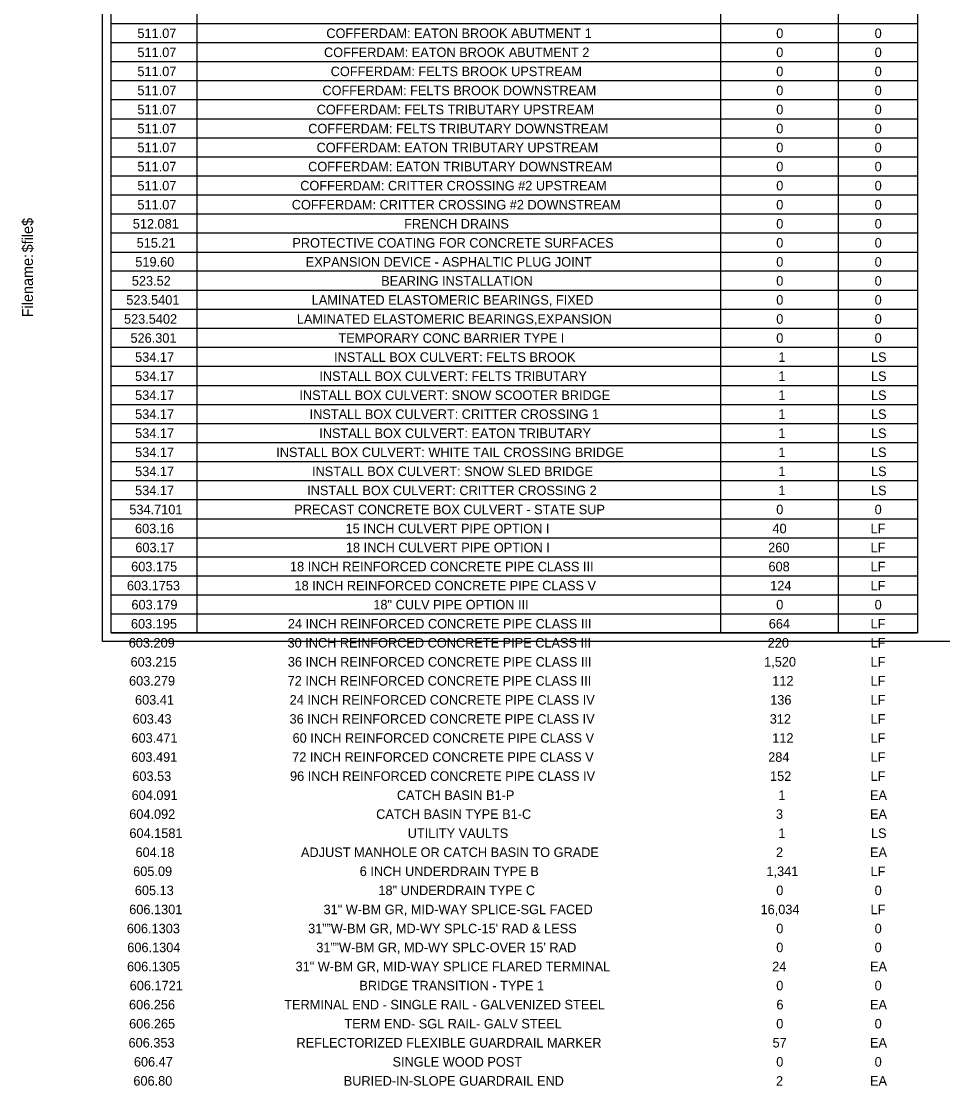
# Model space of a CAD drawing. Extents: x -18.7 to 5.6, y -2.7 to 4.
# Drawn here: x -0.084 to 0.868, y -0.459 to 0.641 of the extents above; entities that cross this region are included whole.
import ezdxf

# ---------------------------------------------------------------- set-up
doc = ezdxf.new("R2010")
doc.units = 0
doc.layers.add('ANNOTATION', color=7, linetype='Continuous')
doc.layers.add('BORDER', color=7, linetype='Continuous')

msp = doc.modelspace()

# ---------------------------------------------------------------- linework, layer by layer
at = {"layer": 'BORDER'}
for p, q in [((0.0974, 1.7215), (0.0974, 0.0088)), ((0.6387, 1.7215), (0.6387, 0.0088)), ((0.7601, 1.7215), (0.7601, 0.0088)), ((0.0088, 0.6388), (0.8421, 0.6388)), ((0.0088, 0.6191), (0.8421, 0.6191)), ((0.0088, 0.5994), (0.8421, 0.5994)), ((0.0088, 0.5797), (0.8421, 0.5797)), ((0.0088, 0.56), (0.8421, 0.56)), ((0.0088, 0.5403), (0.8421, 0.5403)), ((0.0088, 0.5207), (0.8421, 0.5207)), ((0.0088, 0.501), (0.8421, 0.501)), ((0.0088, 0.4813), (0.8421, 0.4813)), ((0.0088, 0.4616), (0.8421, 0.4616)), ((0.0088, 0.4419), (0.8421, 0.4419)), ((0.0088, 0.4222), (0.8421, 0.4222)), ((0.0088, 0.4025), (0.8421, 0.4025)), ((0.0088, 0.3829), (0.8421, 0.3829)), ((0.0088, 0.3632), (0.8421, 0.3632)), ((0.0088, 0.3435), (0.8421, 0.3435)), ((0.0088, 0.3238), (0.8421, 0.3238)), ((0.0088, 0.3041), (0.8421, 0.3041)), ((0.0088, 0.2844), (0.8421, 0.2844)), ((0.0088, 0.2647), (0.8421, 0.2647)), ((0.0088, 0.245), (0.8421, 0.245)), ((0.0088, 0.2254), (0.8421, 0.2254)), ((0.0088, 0.2057), (0.8421, 0.2057)), ((0.0088, 0.186), (0.8421, 0.186)), ((0.0088, 0.1663), (0.8421, 0.1663)), ((0.0088, 0.1466), (0.8421, 0.1466)), ((0.0088, 0.1269), (0.8421, 0.1269)), ((0.0088, 0.1072), (0.8421, 0.1072)), ((0.0088, 0.0876), (0.8421, 0.0876)), ((0.0088, 0.0679), (0.8421, 0.0679)), ((0.0088, 0.0482), (0.8421, 0.0482)), ((0.0088, 0.0285), (0.8421, 0.0285)), ((0.0088, 0.0088), (0.8421, 0.0088))]:
    msp.add_line(p, q, dxfattribs=at)
for points in [[(0, 1.75), (2.6667, 1.75), (2.6667, 0), (0, 0)], [(0.0088, 1.7412), (0.8421, 1.7412), (0.8421, 0.0088), (0.0088, 0.0088)]]:
    msp.add_lwpolyline(points, close=True, dxfattribs=at)

# ---------------------------------------------------------------- texts
at = {"layer": 'ANNOTATION'}
for s, height, p in [('511.07', 0.00984, (0.0361, 0.6237)), ('COFFERDAM: EATON BROOK ABUTMENT 1', 0.009843, (0.2313, 0.6237)), ('0', 0.00984, (0.6962, 0.6237)), ('0', 0.00984, (0.7979, 0.6237)), ('511.07', 0.00984, (0.0361, 0.604)), ('COFFERDAM: EATON BROOK ABUTMENT 2', 0.009843, (0.2289, 0.604)), ('0', 0.00984, (0.6962, 0.604)), ('0', 0.00984, (0.7979, 0.604)), ('511.07', 0.00984, (0.0361, 0.5843)), ('COFFERDAM: FELTS BROOK UPSTREAM', 0.009843, (0.2358, 0.5843)), ('0', 0.00984, (0.6962, 0.5843)), ('0', 0.00984, (0.7979, 0.5843)), ('511.07', 0.00984, (0.0361, 0.5646)), ('COFFERDAM: FELTS BROOK DOWNSTREAM', 0.009843, (0.2272, 0.5646)), ('0', 0.00984, (0.6962, 0.5646)), ('0', 0.00984, (0.7979, 0.5646)), ('511.07', 0.00984, (0.0361, 0.5449)), ('COFFERDAM: FELTS TRIBUTARY UPSTREAM', 0.009843, (0.2213, 0.5449)), ('0', 0.00984, (0.6962, 0.5449)), ('0', 0.00984, (0.7979, 0.5449)), ('511.07', 0.00984, (0.0361, 0.5252)), ('COFFERDAM: FELTS TRIBUTARY DOWNSTREAM', 0.009843, (0.2126, 0.5252)), ('0', 0.00984, (0.6962, 0.5252)), ('0', 0.00984, (0.7979, 0.5252)), ('511.07', 0.00984, (0.0361, 0.5056)), ('COFFERDAM: EATON TRIBUTARY UPSTREAM', 0.009843, (0.2212, 0.5056)), ('0', 0.00984, (0.6962, 0.5056)), ('0', 0.00984, (0.7979, 0.5056)), ('511.07', 0.00984, (0.0361, 0.4859)), ('COFFERDAM: EATON TRIBUTARY DOWNSTREAM', 0.009843, (0.2125, 0.4859)), ('0', 0.00984, (0.6962, 0.4859)), ('0', 0.00984, (0.7979, 0.4859)), ('511.07', 0.00984, (0.0361, 0.4662)), ('COFFERDAM: CRITTER CROSSING #2 UPSTREAM', 0.009843, (0.2043, 0.4662)), ('0', 0.00984, (0.6962, 0.4662)), ('0', 0.00984, (0.7979, 0.4662)), ('511.07', 0.00984, (0.0361, 0.4465)), ('COFFERDAM: CRITTER CROSSING #2 DOWNSTREAM', 0.009843, (0.1956, 0.4465)), ('0', 0.00984, (0.6962, 0.4465)), ('0', 0.00984, (0.7979, 0.4465)), ('512.081', 0.00984, (0.0313, 0.4268)), ('FRENCH DRAINS', 0.009843, (0.3117, 0.4268)), ('0', 0.00984, (0.6962, 0.4268)), ('0', 0.00984, (0.7979, 0.4268)), ('515.21', 0.00984, (0.0353, 0.4071)), ('PROTECTIVE COATING FOR CONCRETE SURFACES', 0.009843, (0.1962, 0.4071)), ('0', 0.00984, (0.6962, 0.4071)), ('0', 0.00984, (0.7979, 0.4071)), ('519.60', 0.00984, (0.0339, 0.3874)), ('EXPANSION DEVICE - ASPHALTIC PLUG JOINT', 0.009843, (0.21, 0.3874)), ('0', 0.00984, (0.6962, 0.3874)), ('0', 0.00984, (0.7979, 0.3874)), ('523.52', 0.00984, (0.0303, 0.3678)), ('BEARING INSTALLATION', 0.009843, (0.288, 0.3678)), ('0', 0.00984, (0.6962, 0.3678)), ('0', 0.00984, (0.7979, 0.3678)), ('523.5401', 0.00984, (0.0246, 0.3481)), ('LAMINATED ELASTOMERIC BEARINGS, FIXED', 0.009843, (0.2162, 0.3481)), ('0', 0.00984, (0.6962, 0.3481)), ('0', 0.00984, (0.7979, 0.3481)), ('523.5402', 0.00984, (0.0222, 0.3284)), ('LAMINATED ELASTOMERIC BEARINGS,EXPANSION', 0.009843, (0.2008, 0.3284)), ('0', 0.00984, (0.6962, 0.3284)), ('0', 0.00984, (0.7979, 0.3284)), ('526.301', 0.00984, (0.0289, 0.3087)), ('TEMPORARY CONC BARRIER TYPE I', 0.009843, (0.2438, 0.3087)), ('0', 0.00984, (0.6962, 0.3087)), ('0', 0.00984, (0.7979, 0.3087)), ('534.17', 0.00984, (0.0337, 0.289)), ('INSTALL BOX CULVERT: FELTS BROOK', 0.009843, (0.2393, 0.289)), ('1', 0.00984, (0.6984, 0.289)), ('LS', 0.00984, (0.7941, 0.289)), ('534.17', 0.00984, (0.0337, 0.2693)), ('INSTALL BOX CULVERT: FELTS TRIBUTARY', 0.009843, (0.2241, 0.2693)), ('1', 0.00984, (0.6984, 0.2693)), ('LS', 0.00984, (0.7941, 0.2693)), ('534.17', 0.00984, (0.0337, 0.2496)), ('INSTALL BOX CULVERT: SNOW SCOOTER BRIDGE', 0.009843, (0.2035, 0.2496)), ('1', 0.00984, (0.6984, 0.2496)), ('LS', 0.00984, (0.7941, 0.2496)), ('534.17', 0.00984, (0.0337, 0.23)), ('INSTALL BOX CULVERT: CRITTER CROSSING 1', 0.009843, (0.214, 0.23)), ('1', 0.00984, (0.6984, 0.23)), ('LS', 0.00984, (0.7941, 0.23)), ('534.17', 0.00984, (0.0337, 0.2103)), ('INSTALL BOX CULVERT: EATON TRIBUTARY', 0.009843, (0.224, 0.2103)), ('1', 0.00984, (0.6984, 0.2103)), ('LS', 0.00984, (0.7941, 0.2103)), ('534.17', 0.00984, (0.0337, 0.1906)), ('INSTALL BOX CULVERT: WHITE TAIL CROSSING BRIDGE', 0.009843, (0.1795, 0.1906)), ('1', 0.00984, (0.6984, 0.1906)), ('LS', 0.00984, (0.7941, 0.1906)), ('534.17', 0.00984, (0.0337, 0.1709)), ('INSTALL BOX CULVERT: SNOW SLED BRIDGE', 0.009843, (0.2165, 0.1709)), ('1', 0.00984, (0.6984, 0.1709)), ('LS', 0.00984, (0.7941, 0.1709)), ('534.17', 0.00984, (0.0337, 0.1512)), ('INSTALL BOX CULVERT: CRITTER CROSSING 2', 0.009843, (0.2115, 0.1512)), ('1', 0.00984, (0.6984, 0.1512)), ('LS', 0.00984, (0.7941, 0.1512)), ('534.7101', 0.00984, (0.0277, 0.1315)), ('PRECAST CONCRETE BOX CULVERT - STATE SUP', 0.009843, (0.1981, 0.1315)), ('0', 0.00984, (0.6962, 0.1315)), ('0', 0.00984, (0.7979, 0.1315)), ('603.16', 0.00984, (0.0336, 0.1118)), ('15 INCH CULVERT PIPE OPTION I', 0.009843, (0.2512, 0.1118)), ('40', 0.00984, (0.6923, 0.1118)), ('LF', 0.00984, (0.7937, 0.1118)), ('603.17', 0.00984, (0.0339, 0.0922)), ('18 INCH CULVERT PIPE OPTION I', 0.009843, (0.2515, 0.0922)), ('260', 0.00984, (0.6879, 0.0922)), ('LF', 0.00984, (0.7937, 0.0922)), ('603.175', 0.00984, (0.0296, 0.0725)), ('18 INCH REINFORCED CONCRETE PIPE CLASS III', 0.009843, (0.1937, 0.0725)), ('608', 0.00984, (0.6882, 0.0725)), ('LF', 0.00984, (0.7937, 0.0725)), ('603.1753', 0.00984, (0.0252, 0.0528)), ('18 INCH REINFORCED CONCRETE PIPE CLASS V', 0.009843, (0.1984, 0.0528)), ('124', 0.00984, (0.69, 0.0528)), ('LF', 0.00984, (0.7937, 0.0528)), ('603.179', 0.00984, (0.0299, 0.0331)), ('18" CULV PIPE OPTION III', 0.009843, (0.2799, 0.0331)), ('0', 0.00984, (0.6962, 0.0331)), ('0', 0.00984, (0.7979, 0.0331)), ('603.195', 0.00984, (0.0294, 0.0134)), ('24 INCH REINFORCED CONCRETE PIPE CLASS III', 0.009843, (0.1915, 0.0134)), ('664', 0.00984, (0.6885, 0.0134)), ('LF', 0.00984, (0.7937, 0.0134)), ('603.209', 0.00984, (0.0271, -0.0063)), ('30 INCH REINFORCED CONCRETE PIPE CLASS III', 0.009843, (0.1912, -0.0063)), ('220', 0.00984, (0.6874, -0.0063)), ('LF', 0.00984, (0.7937, -0.0063)), ('603.215', 0.00984, (0.029, -0.026)), ('36 INCH REINFORCED CONCRETE PIPE CLASS III', 0.009843, (0.1915, -0.026)), ('1,520', 0.00984, (0.6837, -0.026)), ('LF', 0.00984, (0.7937, -0.026)), ('603.279', 0.00984, (0.0274, -0.0456)), ('72 INCH REINFORCED CONCRETE PIPE CLASS III', 0.009843, (0.1913, -0.0456)), ('112', 0.00984, (0.6921, -0.0456)), ('LF', 0.00984, (0.7937, -0.0456)), ('603.41', 0.00984, (0.0336, -0.0653)), ('24 INCH REINFORCED CONCRETE PIPE CLASS IV', 0.009843, (0.1934, -0.0653)), ('136', 0.00984, (0.69, -0.0653)), ('LF', 0.00984, (0.7937, -0.0653)), ('603.43', 0.00984, (0.0311, -0.085)), ('36 INCH REINFORCED CONCRETE PIPE CLASS IV', 0.009843, (0.1933, -0.085)), ('312', 0.00984, (0.6895, -0.085)), ('LF', 0.00984, (0.7937, -0.085)), ('603.471', 0.00984, (0.0299, -0.1047)), ('60 INCH REINFORCED CONCRETE PIPE CLASS V', 0.009843, (0.1964, -0.1047)), ('112', 0.00984, (0.6921, -0.1047)), ('LF', 0.00984, (0.7937, -0.1047)), ('603.491', 0.00984, (0.0297, -0.1244)), ('72 INCH REINFORCED CONCRETE PIPE CLASS V', 0.009843, (0.196, -0.1244)), ('284', 0.00984, (0.6879, -0.1244)), ('LF', 0.00984, (0.7937, -0.1244)), ('603.53', 0.00984, (0.0308, -0.1441)), ('96 INCH REINFORCED CONCRETE PIPE CLASS IV', 0.009843, (0.1938, -0.1441)), ('152', 0.00984, (0.6898, -0.1441)), ('LF', 0.00984, (0.7937, -0.1441)), ('604.091', 0.00984, (0.0301, -0.1638)), ('CATCH BASIN B1-P', 0.009843, (0.3042, -0.1638)), ('1', 0.00984, (0.6984, -0.1638)), ('EA', 0.00984, (0.7931, -0.1638)), ('604.092', 0.00984, (0.0276, -0.1834)), ('CATCH BASIN TYPE B1-C', 0.009843, (0.2828, -0.1834)), ('3', 0.00984, (0.6959, -0.1834)), ('EA', 0.00984, (0.7931, -0.1834)), ('604.1581', 0.00984, (0.0278, -0.2031)), ('UTILITY VAULTS', 0.009843, (0.3154, -0.2031)), ('1', 0.00984, (0.6984, -0.2031)), ('LS', 0.00984, (0.7941, -0.2031)), ('604.18', 0.00984, (0.0341, -0.2228)), ('ADJUST MANHOLE OR CATCH BASIN TO GRADE', 0.009843, (0.2051, -0.2228)), ('2', 0.00984, (0.696, -0.2228)), ('EA', 0.00984, (0.7931, -0.2228)), ('605.09', 0.00984, (0.0317, -0.2425)), ('6 INCH UNDERDRAIN TYPE B', 0.009843, (0.2658, -0.2425)), ('1,341', 0.00984, (0.6861, -0.2425)), ('LF', 0.00984, (0.7937, -0.2425)), ('605.13', 0.00984, (0.0334, -0.2622)), ('18" UNDERDRAIN TYPE C', 0.009843, (0.2851, -0.2622)), ('0', 0.00984, (0.6962, -0.2622)), ('0', 0.00984, (0.7979, -0.2622)), ('606.1301', 0.00984, (0.0276, -0.2819)), ('31" W-BM GR, MID-WAY SPLICE-SGL FACED', 0.009843, (0.2284, -0.2819)), ('16,034', 0.00984, (0.68, -0.2819)), ('LF', 0.00984, (0.7937, -0.2819)), ('606.1303', 0.00984, (0.0251, -0.3016)), ("31””W-BM GR, MD-WY SPLC-15' RAD & LESS", 0.009843, (0.2125, -0.3016)), ('0', 0.00984, (0.6962, -0.3016)), ('0', 0.00984, (0.7979, -0.3016)), ('606.1304', 0.00984, (0.0256, -0.3212)), ("31””W-BM GR, MD-WY SPLC-OVER 15' RAD", 0.009843, (0.2209, -0.3212)), ('0', 0.00984, (0.6962, -0.3212)), ('0', 0.00984, (0.7979, -0.3212)), ('606.1305', 0.00984, (0.0253, -0.3409)), ('31" W-BM GR, MID-WAY SPLICE FLARED TERMINAL', 0.009843, (0.1995, -0.3409)), ('24', 0.00984, (0.692, -0.3409)), ('EA', 0.00984, (0.7931, -0.3409)), ('606.1721', 0.00984, (0.0281, -0.3606)), ('BRIDGE TRANSITION - TYPE 1', 0.009843, (0.2654, -0.3606)), ('0', 0.00984, (0.6962, -0.3606)), ('0', 0.00984, (0.7979, -0.3606)), ('606.256', 0.00984, (0.0274, -0.3803)), ('TERMINAL END - SINGLE RAIL - GALVENIZED STEEL', 0.009843, (0.1878, -0.3803)), ('6', 0.00984, (0.6964, -0.3803)), ('EA', 0.00984, (0.7931, -0.3803)), ('606.265', 0.00984, (0.0275, -0.4)), ('TERM END- SGL RAIL- GALV STEEL', 0.009843, (0.25, -0.4)), ('0', 0.00984, (0.6962, -0.4)), ('0', 0.00984, (0.7979, -0.4)), ('606.353', 0.00984, (0.0269, -0.4197)), ('REFLECTORIZED FLEXIBLE GUARDRAIL MARKER', 0.009843, (0.2004, -0.4197)), ('57', 0.00984, (0.6924, -0.4197)), ('EA', 0.00984, (0.7931, -0.4197)), ('606.47', 0.00984, (0.0324, -0.4394)), ('SINGLE WOOD POST', 0.009843, (0.2997, -0.4394)), ('0', 0.00984, (0.6962, -0.4394)), ('0', 0.00984, (0.7979, -0.4394)), ('606.80', 0.00984, (0.0319, -0.4591)), ('BURIED-IN-SLOPE GUARDRAIL END', 0.009843, (0.2493, -0.4591)), ('2', 0.00984, (0.696, -0.4591)), ('EA', 0.00984, (0.7931, -0.4591))]:
    msp.add_text(s, height=height, dxfattribs=at).set_placement(p)
at = {"layer": 'BORDER'}
for s, p in [('$file$', (-0.0719, 0.4021)), ('Filename:', (-0.0719, 0.335))]:
    msp.add_text(s, height=0.01116, rotation=90, dxfattribs=at).set_placement(p)

doc.saveas('drawing.dxf')
